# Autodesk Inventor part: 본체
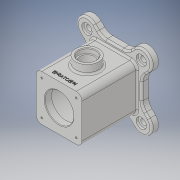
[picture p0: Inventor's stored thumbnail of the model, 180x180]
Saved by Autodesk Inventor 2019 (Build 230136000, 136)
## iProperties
Created: 2021-01
Part Number: 본체
Material: 일반
Document SubType Name: Modeling
Designer: 3dpro8
Density: 1 g/cm^3
Appearance: 기본값
Mass: 385.404 g
Surface Area: 856.309 cm^2
Volume: 385.404 cm^3
Author: 3dpro8
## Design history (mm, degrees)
sketch "스케치1"
  geometry: L1 (40, -40)-(-40, -40); L2 (-40, -40)-(-40, 40); L3 (-40, 40)-(40, 40); L4 (40, 40)-(40, -40); L5 (40, -40)-(-40, 40); L6 (-40, -40)-(40, 40); 1 further point
  constraints: 12 end point, 2 midpoint, 2 parallel, 1 horizontal, 1 perpendicular
  dimensions: "d0" = 80 distance of L2.end L3.end; "d1" = 80 distance of L1.end L2.end
extrude "돌출1" new body sketch "스케치1" distance "d2" = 108; taper "d3" = 0 deg
sketch "스케치4"
  geometry: C1 r 25 at (0, 0); 1 further point
  constraints: 1 centre point, 1 coincident
  dimensions: "d9" = 50 diameter of C1
extrude "돌출2" cut sketch "스케치4" extent not by distance; stored distance "d10" = 0; taper "d11" = 0 deg
node "작업 평면1"
sketch "스케치6"
  geometry: C1 r 35 at (0, 0); 1 further point
  constraints: 1 centre point, 1 coincident
  dimensions: "d13" = 70 diameter of C1
extrude "돌출3" cut sketch "스케치6" stored distance "d14" = 84; taper "d15" = 0 deg
chamfer "모따기1" distance "d16" = 1; stored, may be unused: second distance "d17" = 2, angle "d18" = 45 deg
sketch "스케치7"
  geometry: L1 (30, -30)-(-30, -30); L2 (-30, -30)-(-30, 30); L3 (-30, 30)-(30, 30); L4 (30, 30)-(30, -30); L5 (30, -30)-(-30, 30); L6 (-30, -30)-(30, 30); 1 further point
  constraints: 12 end point, 2 midpoint, 2 parallel, 1 horizontal, 1 perpendicular
  dimensions: "d19" = 60 distance of L2.end L3.end; "d20" = 60 distance of L1.end L2.end
hole "구멍1" sketch "스케치7" at (30, 30), (30, -30) diameter "d21" = 3.242; stored, may be unused: countersink angle "d25" = 90 deg, drill point angle "d27" = 118 deg; dims "d22" = 8, "d23" = 4, "d24" = 2, "d26" = 10
sketch "스케치10"
  geometry: L1 (-48, -48)-(48, -48); L2 (48, -48)-(48, 48); L3 (48, 48)-(-48, 48); L4 (-48, 48)-(-48, -48); L5 (-48, -48)-(48, 48); L6 (48, -48)-(-48, 48); L7 (40, 40)-(-40, 40) reference; L8 (-40, 40)-(-40, -40) reference; L9 (-40, -40)-(40, -40) reference; L10 (40, -40)-(40, 40) reference; 1 further point
  constraints: 12 end point, 2 midpoint, 2 parallel, 1 horizontal, 1 perpendicular
  dimensions: "d31" = 96 distance of L3.end L2.end; "d32" = 96 distance of L2.end L1.end
extrude "돌출4" join sketch "스케치10" distance "d33" = 12; taper "d34" = 0 deg
sketch "스케치11"
  geometry: L1 (0, 0)-(47.376, 47.376); L2 (0, 0)-(67, 0); L3 (48, 48)-(-48, 48) reference; L4 (48, -48)-(48, 48) reference; L5 (34.648, 60.104)-(22.544, 48); L6 (-43.456, -18)-(67, -18); L7 (60.104, 34.648)-(48, 22.544); A1 r 18 centre (47.376, 47.376) between (60.104, 34.648) and (34.648, 60.104)
  constraints: 10 end point, 2 parallel, 2 point on circle, 2 point on line, 2 tangent, 1 centre point, 1 coincident, 1 equal length, 1 horizontal
  dimensions: "d35" = 67 distance of L1.start L1.end; "d36" = 45 deg angle of L2 L1; "d37" = 36 diameter of A1
extrude "돌출5" join sketch "스케치11" distance "d38" = 12; taper "d39" = 0 deg
sketch "스케치12"
  geometry: A1 r 18 centre (47.376, 47.376) between (60.104, 34.648) and (34.648, 60.104) reference; 2 further points
  constraints: 1 coincident
hole "구멍2" sketch "스케치12" at (47.376, 47.376) diameter "d43" = 10; stored, may be unused: countersink angle "d47" = 90 deg, drill point angle "d49" = 118 deg; dims "d44" = 8, "d45" = 18, "d46" = 4, "d48" = 10
node "작업 평면2"
sketch "스케치14"
  geometry: L1 (-22.544, 0)-(22.544, 0) reference; L2 (-22.544, 12)-(22.544, 12) reference; C1 r 20 at (0, 59); 1 further point
  constraints: 1 centre point, 1 vertical alignment
  dimensions: "d56" = 40 diameter of C1; "d91" = 47 distance from line of L2 C1.centre
extrude "돌출6" join sketch "스케치14" stored distance "d58" = 10; taper "d59" = 0 deg
sketch "스케치15"
  geometry: C1 r 20 at (0, 0) reference; 2 further points
  constraints: 1 coincident
hole "구멍3" sketch "스케치15" at (0, 0) diameter "d60" = 25; stored, may be unused: countersink angle "d64" = 90 deg, drill point angle "d66" = 0 deg; dims "d61" = 6, "d62" = 30, "d63" = 8, "d65" = 8
fillet "모깎기1" dims "d67" = 2
chamfer "모따기2" distance "d68" = 1; stored, may be unused: second distance "d69" = 2, angle "d70" = 45 deg
chamfer "모따기3" distance "d71" = 1; stored, may be unused: second distance "d72" = 2, angle "d73" = 45 deg
sketch "스케치16"
  geometry: 1 further point
sketch "스케치17"
  geometry: L1 (-30, 30)-(30, 30); L2 (30, 30)-(30, -30); L3 (30, -30)-(-30, -30); L4 (-30, -30)-(-30, 30); L5 (-30, 30)-(30, -30); L6 (30, 30)-(-30, -30); 3 further points
  constraints: 12 end point, 2 coincident, 2 midpoint, 2 parallel, 1 horizontal, 1 perpendicular
  dimensions: "d74" = 60 distance of L2.end L3.end; "d75" = 60 distance of L1.end L2.end
hole "구멍4" sketch "스케치17" at (-30, 30), (-30, -30) diameter "d76" = 3.242; stored, may be unused: countersink angle "d80" = 90 deg, drill point angle "d82" = 118 deg; dims "d77" = 8, "d78" = 4, "d79" = 2, "d81" = 10
sketch "스케치18"
  geometry: L1 (80, 0)-(0, 0) reference; L2 (75, 14)-(5, 14) reference; L3 (5, 94)-(75, 94) reference; 4 further points
  constraints: 1 midpoint, 1 vertical alignment, 2 other
  dimensions: "d83" = 10 distance from line of point (40, 10) L1
feature "엠보싱1" sketch "스케치18" dims "d0" = 80, "d1" = 80, "d84" = 0.5, "d85" = 0
fillet "모깎기2" dims "d86" = 10
fillet "모깎기4" dims "d88" = 20
fillet "모깎기5" dims "d89" = 3
fillet "모깎기6" dims "d90" = 3
fillet "모깎기7" dims "d92" = 3
node "솔리드1"
mirror "미러1"
pattern_circular "원형 패턴1" dims angle "d41" = 360 deg
pattern_circular "원형 패턴2" dims angle "d51" = 360 deg
mirror "미러2"
node "투영된 루프1"
other parameters: "d12" = 54, "d55" = 55
